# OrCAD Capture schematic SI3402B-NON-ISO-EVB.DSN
size A; title: Si3402 Eval Board - Isolated; rev: 2.1; note: SI3402B-NON-ISO-EVB
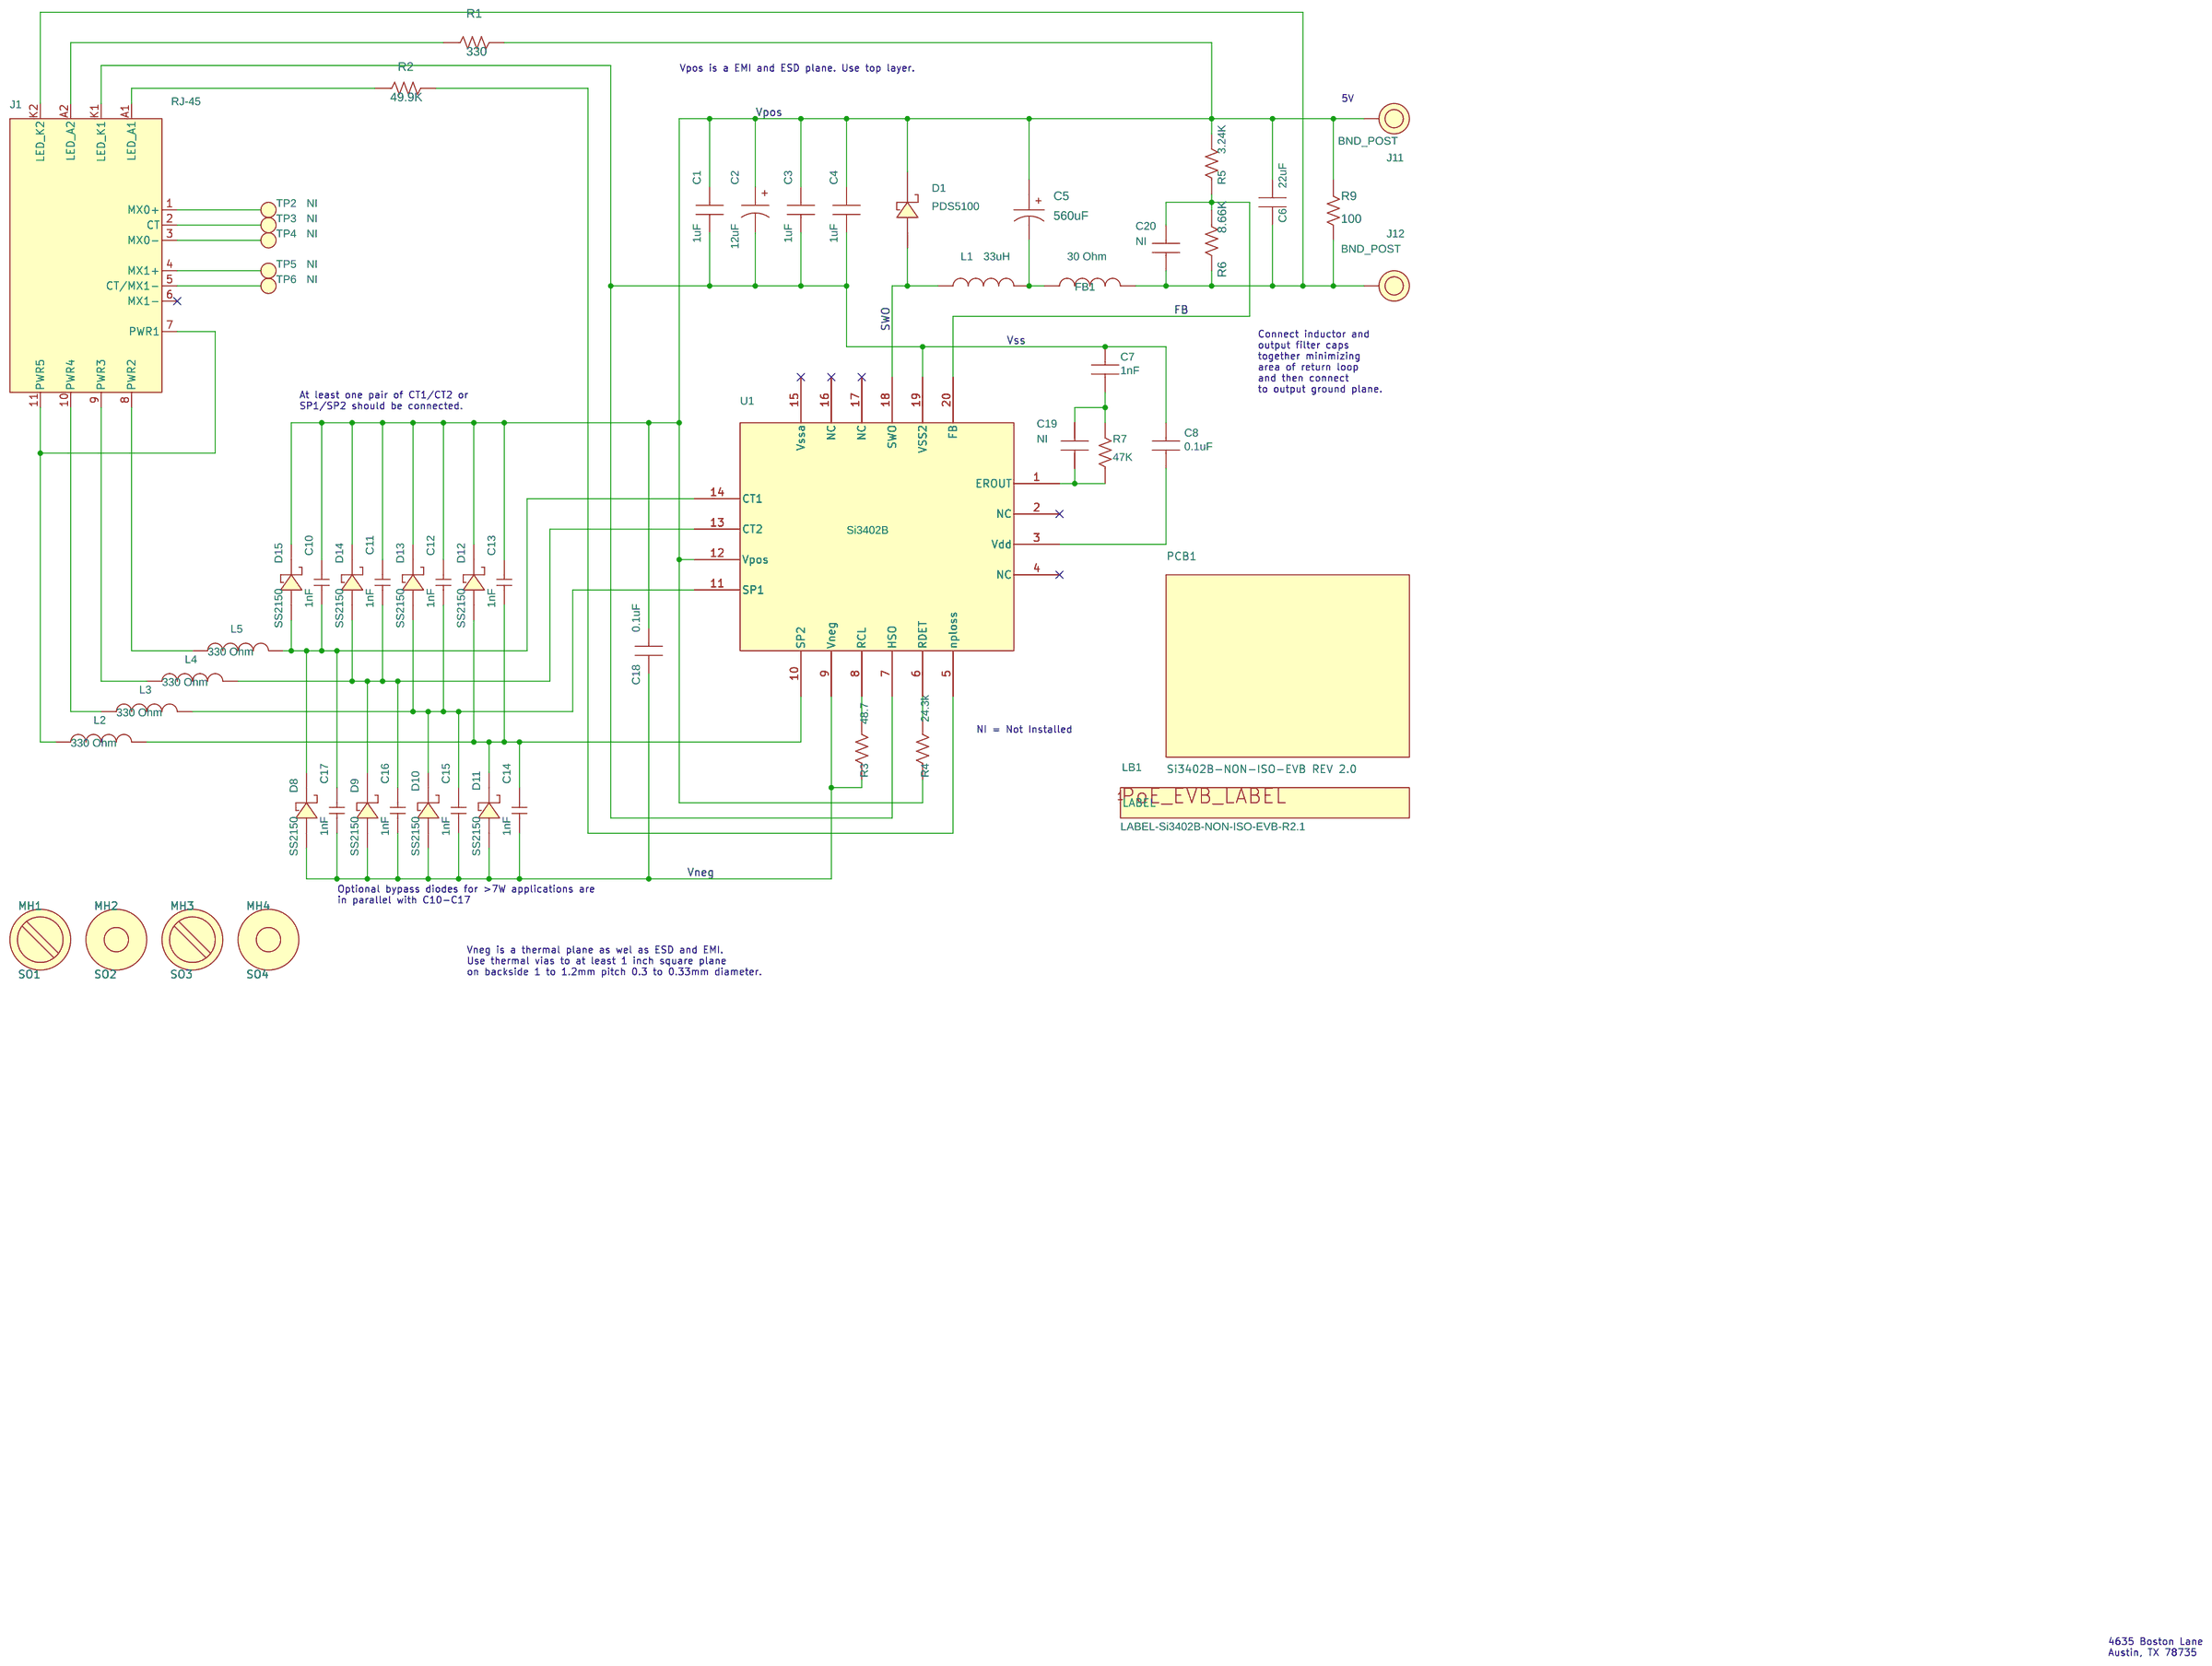
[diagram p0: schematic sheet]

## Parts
C1  1uF  [C1210]
C2  12uF  [C2.5X6.3MM-RAD]
C3  1uF  [C1210]
C4  1uF  [C1210]
C5  560uF  [C3.5X8MM-RAD]
C6  22uF  [C0805]
C7  1nF  [C0805]
C8  0.1uF  [C0805]
C10  1nF  [C0603]
C11  1nF  [C0603]
C12  1nF  [C0603]
C13  1nF  [C0603]
C14  1nF  [C0603]
C15  1nF  [C0603]
C16  1nF  [C0603]
C17  1nF  [C0603]
C18  0.1uF  [C0805]
C19  150pF  [C0805]
C20  3.3nF  [C0805]
D1  PDS5100  [POWERDI-5]
D8  SS2150  [DO-214]
D9  SS2150  [DO-214]
D10  SS2150  [DO-214]
D11  SS2150  [DO-214]
D12  SS2150  [DO-214]
D13  SS2150  [DO-214]
D14  SS2150  [DO-214]
D15  SS2150  [DO-214]
FB1  30 Ohm  [L0805]
J1  RJ-45  [RJ45-SI-52004]
J11  BND_POST  [BANANA-JACK]
J12  BND_POST  [BANANA-JACK]
L1  33uH  [IND-SPD]
L2  330 Ohm  [L0805]
L3  330 Ohm  [L0805]
L4  330 Ohm  [L0805]
L5  330 Ohm  [L0805]
LB1  LABEL-Si3402B-NON-ISO-EVB-R2.1  [PTL-14-717]
MH1  4-40  [MH-125NP]
MH2  4-40  [MH-125NP]
MH3  4-40  [MH-125NP]
MH4  4-40  [MH-125NP]
PCB1  Si3402B-NON-ISO-EVB REV 2.0  [N/A]
R1  330  [R0805]
R2  49.9K  [R0805]
R3  48.7  [R0805]
R4  24.3k  [R0805]
R5  3.24K  [R0805]
R6  8.66K  [R0805]
R7  47K  [R0805]
R9  100  [R1210]
SO1  STANDOFF
SO2  STANDOFF
SO3  STANDOFF
SO4  STANDOFF
TP2  BLACK  [TESTPOINT]
TP3  BLACK  [TESTPOINT]
TP4  BLACK  [TESTPOINT]
TP5  BLACK  [TESTPOINT]
TP6  BLACK  [TESTPOINT]
U1  Si3402B  [QFN20N5X5P0.8]

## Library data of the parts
C1 C3 C4 = CAP_NP: CAP, 1uF, 100V, ±10%, X7R, 1210; Manufacturer: Venkel; ManufacturerPN: C1210X7R101-105K; SiLabsPN: C1210X7R101-105K; Tolerance: ±10%; Type: X7R; Voltage: 100V; Datasheet: PID_C.pdf
C2 = CAP_POL_ALT: CAP, 12uF, 100V, ±20%, AL, 6.3X11.2MM; Manufacturer: Panasonic; ManufacturerPN: EEUFC2A120; SiLabsPN: EEUFC2A120; Tolerance: ±20%; Type: Alum_Elec; Voltage: 100V; Datasheet: ABA0000CE22.pdf
C5 = CAP_POL: CAP, 560uF, 6.3V, ±20%, AL, 8.0X11.5MM; Manufacturer: Panasonic; ManufacturerPN: EEUFM0J561; Part_Type: CAP/POL; SiLabsPN: EEUFM0J561; Tolerance: ±20%; Type: Alum_Elec; Voltage: 6.3V; Datasheet: ABA0000CE108.pdf
C6 = CAP_NP: CAP, 22uF, 6.3V, ±20%, X5R, 0805; Manufacturer: Venkel; ManufacturerPN: C0805X5R6R3-226M; SiLabsPN: C0805X5R6R3-226M; Tolerance: ±20%; Type: X5R; Voltage: 6.3V; Datasheet: PID_C.pdf
C7 = CAP_NP: CAP, 1nF, 50V, ±1%, C0G, 0805; Manufacturer: Venkel; ManufacturerPN: C0805C0G500-102F; SiLabsPN: C0805C0G500-102F; Tolerance: ±1%; Type: C0G; Voltage: 50V; Datasheet: PID_C.pdf
C8 = CAP_NP: CAP, 0.1uF, 16V, ±10%, X7R, 0805; Manufacturer: Venkel; ManufacturerPN: C0805X7R160-104K; SiLabsPN: C0805X7R160-104K; Tolerance: ±10%; Type: X7R; Voltage: 16V; Datasheet: PID_C.pdf
C10-C17 = CAP_NP_SMALL: CAP, 1nF, 100V, ±10%, X7R, 0603; Manufacturer: Venkel; ManufacturerPN: C0603X7R101-102K; Part_Type: CAP/NP; SiLabsPN: C0603X7R101-102K; Tolerance: ±10%; Type: X7R; Voltage: 100V; Datasheet: PID_C.pdf
C18 = CAP_NP: CAP, 0.1uF, 100V, ±10%, X7R, 0805; Manufacturer: Venkel; ManufacturerPN: C0805X7R101-104K; SiLabsPN: C0805X7R101-104K; Tolerance: ±10%; Type: X7R; Voltage: 100V; Datasheet: PID_C.pdf
C19 = CAP_NP: CAP, 150pF, 16V, ±10%, X7R, 0805; Installed component: NI; Manufacturer: Venkel; ManufacturerPN: C0805X7R160-151K; SiLabsPN: C0805X7R160-151K; Tolerance: ±10%; Type: X7R; Voltage: 16V; Datasheet: PID_C.pdf
C20 = CAP_NP: CAP, 3.3nF, 16V, ±10%, X7R, 0805; Installed component: NI; Manufacturer: Venkel; ManufacturerPN: C0805X7R160-332K; SiLabsPN: C0805X7R160-332K; Tolerance: ±10%; Type: X7R; Voltage: 16V; Datasheet: PID_C.pdf
D1 = DIODE_SCHOTTKY_DUAL_ANODE_3PIN: DIO, SCHOTTKY, 100V, 5A, PowerDI-5; Manufacturer: Diodes Inc.; ManufacturerPN: PDS5100H-13; Rating: 5A; SiLabsPN: PDS5100H-13; Type: Schottky; Voltage: 100V; Datasheet: ds30471.pdf
D8-D15 = DIODE_SCHOTTKY: DIO, SINGLE, 150V, 2A, DO-214; Manufacturer: MCC; ManufacturerPN: SS2150-LTP; Rating: 2A; SiLabsPN: SS2150-LTP; Type: Single; Voltage: 150V; Datasheet: SS22-L-SS2150-L(DO-214)-478019.pdf
FB1 = Ferrite_Bead: FERRITE BEAD, 30 Ohm @100MHZ, 0805; Manufacturer: MuRata; ManufacturerPN: BLM21PG300SN1; Part_Type: IND/FB; Rating: 3000mA; SiLabsPN: BLM21PG300SN1; Type: SMT; Datasheet: Murata BLM Ferrites.pdf
J1 = MAGJACK_3: CONN, RJ-45, MAGJACK, 1 Port PoE; Manufacturer: Bel; ManufacturerPN: SI-52003-F; SiLabsPN: SI-52003-F; Type: Receptacle; Datasheet: SI-52003-F.pdf
J11 J12 = BINDING-POST: CONN, BANANA JACK, Threaded uninsulated; Manufacturer: ABBATRON HH SMITH; ManufacturerPN: 101; Part_Type: CON; Rating: 15A; SiLabsPN: 101; Type: BANANA; Datasheet: SD-101.pdf
L1 = INDUCTOR: INDUCTOR, POWER, Shielded; Manufacturer: Coilcraft; ManufacturerPN: MSS1278-333ML; Part_Type: IND/SMT; Rating: 5.2A; SiLabsPN: MSS1278-333ML; Tolerance: ±20%; Type: Shielded; Datasheet: mss1278.pdf
L2-L5 = Ferrite_Bead: FERRITE BEAD, 330 Ohm @100MHZ, 0805; Manufacturer: MuRata; ManufacturerPN: BLM21PG331SN1; Part_Type: IND/FB; Rating: 1500mA; SiLabsPN: BLM21PG331SN1; Type: SMT; Datasheet: Murata BLM Ferrites.pdf
LB1 = PoE_EVB_Label: LABEL, PDB, POLYIMIDE, WHITE, 1.00 in. X 0.187 in., FONT 2; Manufacturer: Skyworks; Type: POLYIMIDE, WHITE; Datasheet: Brady TLS2200 Label PTL-14-717.pdf
MH1-MH4 = SCREW-Small: HDW, SCREW, 4-40 x 1/4 in. Pan Head, Slotted, Nylon; Manufacturer: Richco Plastic Co; ManufacturerPN: NSS-4-4-01; SiLabsPN: NSS-4-4-01; Type: SCREW; Datasheet: RichcoPlasticCo_Screws.pdf
PCB1 = PCB: PCB, BARE BOARD, Si3402B-NON-ISO-EVB REV 2.0; Manufacturer: Skyworks; Type: BARE PCB
R1 = RES_V: RES, 330 Ohm, 1/10W, ±1%, ThickFilm, 0805; Manufacturer: Venkel; ManufacturerPN: CR0805-10W-3300F; Part_Type: RES/SMT; Rating: 1/10W; SiLabsPN: CR0805-10W-3300F; Tolerance: ±1%; Type: ThickFilm; Datasheet: PID_CR.pdf
R2 = RES_V: RES, 49.9K, 1/8W, ±1%, ThickFilm, 0805; Manufacturer: Venkel; ManufacturerPN: CR0805-8W-4992F; Part_Type: RES/SMT; Rating: 1/8W; SiLabsPN: CR0805-8W-4992F; Tolerance: ±1%; Type: ThickFilm; Datasheet: PID_CR.pdf
R3 = RES: RES, 48.7 Ohm, 1/8W, ±1%, ThickFilm, 0805; Manufacturer: vishay; ManufacturerPN: CRCW080548R7FKTA; Rating: 1/8W; SiLabsPN: CR0805-8W-48R7F; Tolerance: ±1%; Type: ThickFilm; Datasheet: dcrcwe3-109170.pdf
R4 = RES: RES, 24.3k, 1/8W, ±1%, ThickFilm, 0805; Manufacturer: vishay; ManufacturerPN: CRCW080524K3FKEA; Rating: 1/8W; SiLabsPN: CR0805-8W-2432F; Tolerance: ±1%; Type: ThickFilm; Datasheet: dcrcwe3-109170.pdf
R5 = RES_V: RES, 3.24K, 1/8W, ±1%, ThickFilm, 0805; Manufacturer: Vishay; ManufacturerPN: CRCW08053K24FKEA; Part_Type: RES/SMT; Rating: 1/8W; SiLabsPN: CR0805-8W-3241F; Tolerance: ±1%; Type: ThickFilm; Datasheet: dcrcwe3-109170.pdf
R6 = RES_V: RES, 8.66K, 1/10W, ±1%, ThickFilm, 0805; Manufacturer: Venkel; ManufacturerPN: CR080510W-8661F; Part_Type: RES/SMT; Rating: 1/10W; SiLabsPN: CR080510W-8661F; Tolerance: ±1%; Type: ThickFilm; Datasheet: PID_CR.pdf
R7 = RES: RES, 47K, 1/10W, ±5%, ThickFilm, 0805; Manufacturer: Venkel; ManufacturerPN: CR0805-10W-473J; Rating: 1/10W; SiLabsPN: CR0805-10W-473J; Tolerance: ±5%; Type: ThickFilm; Datasheet: PID_CR.pdf
R9 = RES_V: RES, 100 Ohm, 1/2W, ±1%, ThickFilm, 1210; Manufacturer: Venkel; ManufacturerPN: CR1210-2W-1000F; Part_Type: RES/SMT; Rating: 1/2W; SiLabsPN: CR1210-2W-1000F; Tolerance: ±1%; Type: ThickFilm; Datasheet: PID_CR.pdf
SO1-SO4 = STANDOFF: HDW, STANDOFF, 4-40 X 1/2" , Nylon; Manufacturer: SPC Technology; ManufacturerPN: 2397; SiLabsPN: 2397; Datasheet: SPC_Technology_spacers.pdf
TP2-TP6 = TEST_POINT: TESTPOINT, BLACK, 0.050" LOOP, PTH; Installed component: NI; Manufacturer: Keystone; ManufacturerPN: 5001; SiLabsPN: 5001; Silk: <Silk>; Type: LOOP; Datasheet: Keystone_thm_datasheet.pdf
U1 = Si3402B: IC, FULLY-INTEGRATED 802.3-COMPLIANT PD INTERFACE AND SWITCHING REGULATOR, QFN20; Manufacturer: Skyworks; Type: PD; Voltage: 100; Datasheet: Si3402Rev1_0.pdf

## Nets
Vss: C1.1 C2.2 C3.1 C4.1 C7.1 C8.1 J1.K1(LED) U1.7(HSO) U1.19(VSS2)
FB: C20.1 R5.2 R6.2 U1.20(FB)
LABEL: LB1.1(LABEL)
SWO: D1.A1(ANODE) D1.A2(ANODE) L1.1 U1.18(SWO)
Vneg: C14.1 C15.1 C16.1 C17.1 C18.2 D8.A(ANODE) D9.A(ANODE) D10.A(ANODE) D11.A(ANODE) R3.1 U1.9(Vneg)
Vpos: C1.2 C2.1 C3.2 C4.2 C5.1 C6.1 C10.2 C11.2 C12.2 C13.2 C18.1 D1.K(CATHODE) D12.K(CATHODE) D13.K(CATHODE) D14.K(CATHODE) D15.K(CATHODE) J11.1(BP) R1.1 R4.1 R5.1 R9.2 U1.12(Vpos)
N198190: C10.1 C17.2 D8.K(CATHODE) D15.A(ANODE) L5.2 U1.14(CT1)
N198198: C11.1 C16.2 D9.K(CATHODE) D14.A(ANODE) L4.2 U1.13(CT2)
N198214: C12.1 C15.2 D10.K(CATHODE) D13.A(ANODE) L3.2 U1.11(SP1)
N198242: C13.1 C14.2 D11.K(CATHODE) D12.A(ANODE) L2.2 U1.10(SP2)
N209690: C6.2 C20.2 FB1.2 J1.K2(LED) J12.1(BP) R6.1 R9.1
N316737: R2.1 U1.5(nploss)
N317144: J1.A1(LED) R2.2
N717681: C8.2 U1.3(Vdd)
N781715: C7.2 C19.1 R7.2
N782500: C19.2 R7.1 U1.1(EROUT)
N1344300: J1.A2(LED) R1.2
N1366006: C5.2 FB1.1 L1.2
N1383049: J1.8(PWR2) L5.1
N1386195: J1.9(PWR3) L4.1
N1386202: J1.10(PWR4) L3.1
N1387215: R4.2 U1.6(RDET)
N1391676: R3.2 U1.8(RCL)
N1411783: J1.2(CT) TP3.1(Point)
N1411787: J1.3(MX0-) TP4.1(Point)
N1411802: J1.4(MX1+) TP5.1(Point)
N1411806: J1.5(CT/MX1-) TP6.1(Point)
N1411830: J1.1(MX0+) TP2.1(Point)
N1415222: J1.7(PWR1) J1.11(PWR5) L2.1

Not connected (* = marked no-connect by the designer): J1 6(MX1-)*; U1 2(NC)* 4(NC)* 15(Vssa)* 16(NC)* 17(NC)*

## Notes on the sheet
- Vpos is a EMI and ESD plane. Use top layer.
- 5V
- Connect inductor and
  output filter caps
  together minimizing
  area of return loop
  and then connect
  to output ground plane.
- At least one pair of CT1/CT2 or
  SP1/SP2 should be connected.
- NI = Not Installed
- Optional bypass diodes for >7W applications are
  in parallel with C10-C17
- Vneg is a thermal plane as wel as ESD and EMI.
  Use thermal vias to at least 1 inch square plane
  on backside 1 to 1.2mm pitch 0.3 to 0.33mm diameter.
- 4635 Boston Lane
  Austin, TX 78735
